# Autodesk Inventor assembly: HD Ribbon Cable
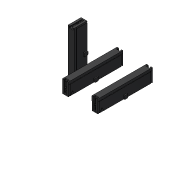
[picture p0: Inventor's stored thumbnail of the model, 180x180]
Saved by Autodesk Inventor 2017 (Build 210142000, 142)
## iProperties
Created: 2007-02
Part Number: HD Ribbon Cable
Document SubType Name: Assembly
Designer: DanielSeverino
Author: DanielSeverino
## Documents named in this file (2)
- C:\Users\DanielSeverino\Desktop\01\HD Ribbon Cable.iam
- C:\Users\DanielSeverino\Desktop\01\Ribbon Cable Connector.ipt
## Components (3 placed, 1 different names)
1. Ribbon Cable Connector:1
2. Ribbon Cable Connector:2
3. Ribbon Cable Connector:3
